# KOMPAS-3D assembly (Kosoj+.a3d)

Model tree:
1. Эскиз:3
2. Точка:5
     X = -49.8; Y = 15; Z = 64.9935; Координата X = -49.8; Координата Y = 15; Координата Z = 64.9935
3. Сплайн:1
     Порядок = 4
4. Эскиз:4
5. Точка:6
     X = -49.8; Y = 15; Z = 96.9935; Координата X = -49.8; Координата Y = 15; Координата Z = 96.9935
6. Сплайн:2
     Порядок = 4
7. Эскиз:8
8. Эскиз:9
9. Точка:8
     X = -32.7; Y = 15; Z = 82.0935; Координата X = -32.7; Координата Y = 15; Координата Z = 82.0935
10. Точка:9
     X = -32.7; Y = 15; Z = 50.0935; Координата X = -32.7; Координата Y = 15; Координата Z = 50.0935
11. Точка:26
     X = -30; Y = 69.75; Z = 56
12. Точка:27
     X = -30; Z = 56
13. Точка:28
     X = -18.4659; Y = 29.8568; Z = 78.5
14. Точка:29
     X = 17.0734; Y = 30.0738; Z = 78.5
15. Сплайн:12
     Порядок = 4
16. Эскиз:17
17. Кинематическая операция:16
     Толщина стенки 1 = 1; Толщина стенки 2 = 1
18. Сплайн:13
     Порядок = 4
19. Эскиз:18
20. Кинематическая операция:17
     Толщина стенки 1 = 1; Толщина стенки 2 = 1
21. Точка:30
     X = -0.83483; Y = 70; Z = 117.219
22. Сплайн:15
     Порядок = 4
23. Массив по сетке:2  (labels: Экземпляр ( 2, 1 ))
     N 1 = 2; Шаг 1 = 80; Угол раствора = 90; N 2 = 1
24. Точка:31
     X = -2.5359; Y = 59.3; Z = 80.5
25. Точка:33
     X = -22.5; Y = 31.5; Z = 157.5
26. Точка:34
     X = -36; Z = 273.926
27. Сплайн:18
     Порядок = 4
28. Эскиз:21
29. Точка:35
     X = 4; Y = 29.5; Z = 183.5
30. Точка:36
     X = 36; Z = 273.926
31. Сплайн:19
     Порядок = 4
32. Эскиз:22
33. Кинематическая операция:21
     Толщина стенки 1 = 1; Толщина стенки 2 = 1
34. Эскиз:23
35. Кинематическая операция:22
     Толщина стенки 1 = 1; Толщина стенки 2 = 1
36. Кинематическая операция:23
     Толщина стенки 1 = 1; Толщина стенки 2 = 1
37. Эскиз:24
38. Точка:37
     X = -50; Y = -66; Z = 273.926
39. Точка:38
     X = -8.60832; Y = -70.6747; Z = 224.733
40. Сплайн:20
     Порядок = 4
41. Кинематическая операция:24
     Толщина стенки 1 = 1; Толщина стенки 2 = 1
42. Точка:39
     X = -3.89269; Y = -67.9178; Z = 224.733
43. Точка:40
     X = 23.5; Y = 27.5; Z = 202.5
44. Сплайн:21
     Порядок = 4
45. Эскиз:25
46. Кинематическая операция:25
     Толщина стенки 1 = 1; Толщина стенки 2 = 1
47. Точка:41
     X = 45.4203; Y = 27.5; Z = 157.42
48. Точка:42
     X = 50; Y = -66; Z = 273.926
49. Сплайн:22
     Порядок = 4
50. Эскиз:26
51. Кинематическая операция:26
     Толщина стенки 1 = 1; Толщина стенки 2 = 1
52. Эскиз:27
53. Точка:43
     X = -0.793376; Y = 70; Z = 111.932
54. Сплайн:23
     Порядок = 4
55. Точка:45
     X = -25; Y = 9; Z = 14; Координата X = -25; Координата Y = 9; Координата Z = 14
56. Сплайн:29
     Порядок = 4
57. Кинематическая операция:32
     Толщина стенки 1 = 1; Толщина стенки 2 = 1
58. Эскиз:29
59. Точка:47
     X = -28.18; Y = 4; Z = 13.8
60. Сплайн:30
     Порядок = 4
61. Точка:48
     X = -5.4; Y = 23.6; Z = 8
62. Точка:49
     X = 21.91; Y = 23.6; Z = -8
63. Сплайн:31
     Порядок = 4
64. Сплайн:32
     Порядок = 4
65. Эскиз:30
66. Кинематическая операция:34
     Толщина стенки 1 = 1; Толщина стенки 2 = 1
67. Эскиз:31
68. Кинематическая операция:35
     Толщина стенки 1 = 1; Толщина стенки 2 = 1
69. Точка:50
     X = 55; Y = -138.8; Z = 79.5
70. Смещенная плоскость:1
     Расстояние = 80
71. Точка:51
     X = -22; Y = 7.3; Z = -35.75
72. Точка:52
     X = -22; Y = 7.3; Z = 35.75
73. Массив по сетке:3  (labels: Экземпляр ( 2, 1 ); Экземпляр ( 3, 1 ); Экземпляр ( 4, 1 ))
     N 1 = 4; Шаг 1 = 36.8; Угол раствора = 90; N 2 = 1
74. Массив по сетке:4  (labels: Экземпляр ( 2, 1 ); Экземпляр ( 3, 1 ))
     N 1 = 3; Шаг 1 = 36.8; Угол раствора = 90; N 2 = 1; Расстояние = 10; Расстояние = 23.75; Расстояние = -32; Расстояние = 40; Расстояние = 3; Расстояние = 15; Расстояние = -15; Расстояние = -34; Расстояние = -50; Расстояние = 80; Угол = 150; Расстояние = -50; Угол = 45; Расстояние = 3; Расстояние = 1; Расстояние = -1; Расстояние = 1; Расстояние = 57; Расстояние = -93; Расстояние = -120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

Referenced files in C:\Users\Oleg\Documents\Разработки\Сварка\мой СЭМ\Компас\: SSNT 3440 - радиатор .m3d, 470mFx400.m3d, KBPC.m3d, К73-17.m3d, Cooler 120х120.m3d, SSNT 3440 - радиатор D.m3d, 150EBU_гнутый.m3d, GA200HS60.m3d, E70_33_32.m3d, Дроссель 15 витьков.a3d, Клемма 6.m3d, Клемма угловая.m3d, Клемма EBU.m3d, Клемма 150А.m3d, Плата индикации.m3d, Клемма Э.m3d, Клемма 8.m3d, Клемма 8У.m3d, Дроссель 11 витьков.a3d, ПП выход СБ.a3d, Клемма 4.m3d, Тор 32х20х9.m3d, Подложка.m3d, Дистанер.m3d, ПП кондёров.m3d
Referenced files in C:\Program Files (x86)\ASCON\KOMPAS-3D V12\Libs\: constr3d.l3d
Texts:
  Шайбы|Шайба_1
  Шайбы|Шайба_2
  Гайки|Гайка_1
  Болты|Болт_1
  SSNT-3430
  Шайба 5 ГОСТ 11371-78
  Винт М5x20 ГОСТ 11644-80
  head2
  head4
  groove1
  fillet4
  head3
  groove4
  fillet1
  groove2
  groove3
  fillet2
  groove5
  head1
  fillet3
  Шайба 3 ГОСТ 11371-78
  Винт М3x10 ГОСТ 11644-80
  Винт М5x30 ГОСТ 1491-80
  Шайба 5 Н ГОСТ 6402-70
  Гайка М5 ГОСТ 5915-70
  Винт М5x16 ГОСТ 1491-80
  Шайба 6 ГОСТ 11371-78
  Винт М6x16 ГОСТ 1491-80
  Гайка М6 ГОСТ 5915-70
  Шайба 8 ГОСТ 11371-78
  Шайба 8 Н ГОСТ 6402-70
  Болт М8х10 ГОСТ 15589-70
  Винт М3x8 ГОСТ 1491-80
  Шайба 4 ГОСТ 11371-78
  Винт М4x8 ГОСТ 11738-84
  Болт М5х14 ГОСТ 7805-70
  Гайка М4 ГОСТ 5915-70
  Винт М4x10 ГОСТ 17475-80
